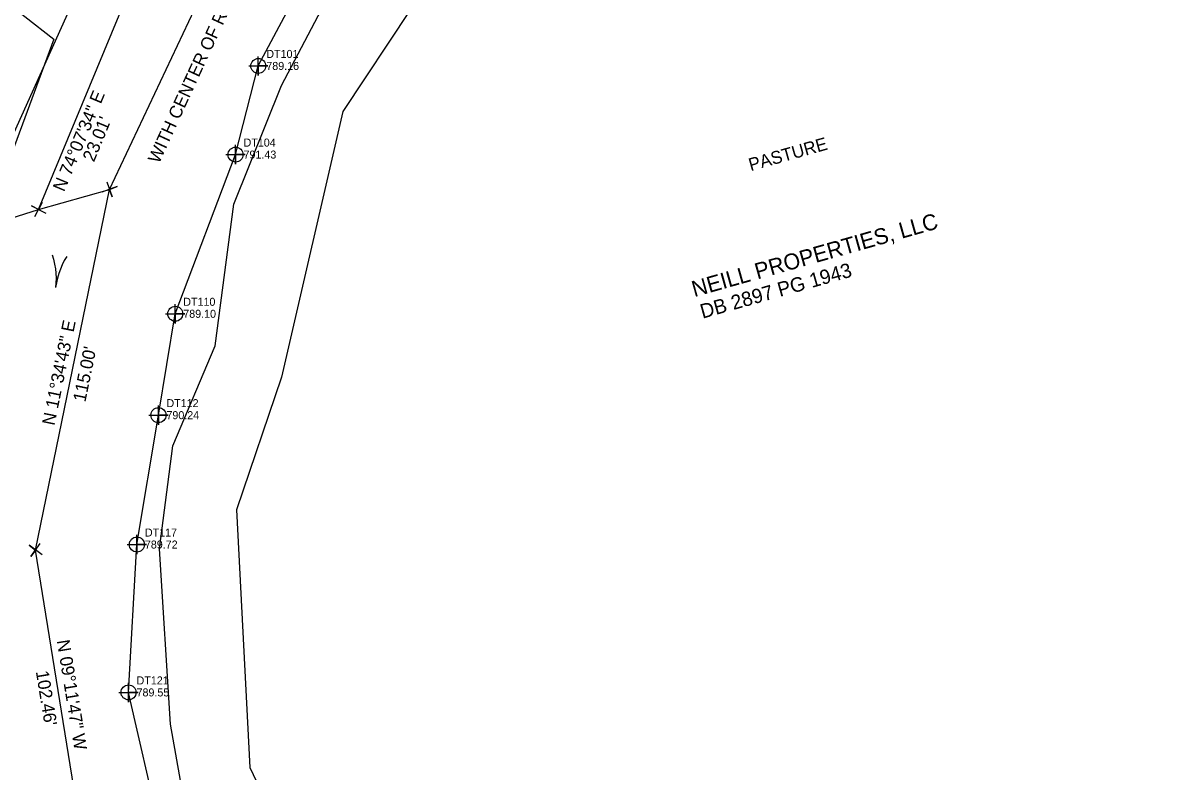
# Model space of a CAD drawing. Extents: x 1316460 to 1321645, y 684173 to 687077.
# Drawn here: x 1319517 to 1319876.5, y 685658.1 to 685892 of the extents above; entities that cross this region are included whole.
import ezdxf

# ---------------------------------------------------------------- set-up
doc = ezdxf.new("R2010")
doc.units = 0
for name, color, linetype in [('Exist Hydro River Flow Arrow CELL', 7, 'Continuous'), ('Exist Hydro Stream Flow Arrow CELL', 7, 'Continuous'), ('Exist Hydro Stream or Body of Water Cogo Elevation', 7, 'Continuous'), ('Exist Hydro Stream or Body of Water Cogo Number', 7, 'Continuous'), ('Exist Hydro Stream or Body of Water Cogo Point CELL', 7, 'Continuous'), ('Exist Hydrographic Water Edge Cogo Elevation', 7, 'Continuous'), ('Exist Property Corner CELL', 7, 'Continuous'), ('Exist Property Deed Book Text', 7, 'Continuous'), ('Exist Property Line', 7, 'Continuous'), ('Exist Property Line Text', 7, 'Continuous'), ('Exist Property Owner Text', 7, 'Continuous'), ('Exist Vegetation Woods Line', 7, 'Continuous'), ('Exist Vegetation Woods Line Text', 7, 'Continuous')]:
    doc.layers.add(name, color=color, linetype=linetype)

# ---------------------------------------------------------------- blocks, each defined once
blk = doc.blocks.new('EXIST HYDRO STREAM FLOW ARROW')
at = {"layer": 'Exist Hydro Stream Flow Arrow CELL'}
blk.add_line((0, 0), (0, 0), dxfattribs=at)
for points in [[(-0.1, 0.04575), (-0.07325, 0.03375), (-0.04475, 0.0245), (-0.0165, 0.01575), (0.01175, 0.0095), (0.041, 0.00475), (0.07075, 0.0015), (0.1, 0)], [(-0.1, -0.04575), (-0.07325, -0.03375), (-0.04475, -0.0245), (-0.0165, -0.01575), (0.01175, -0.0095), (0.041, -0.00475), (0.07075, -0.0015), (0.1, 0)]]:
    blk.add_lwpolyline(points, dxfattribs=at)

msp = doc.modelspace()

# ---------------------------------------------------------------- linework, layer by layer
at = {"layer": 'Exist Hydro Stream or Body of Water Cogo Point CELL'}
for points in [[(1319587.45, 685878.64), (1319593.45, 685878.64), (1319590.45, 685878.64), (1319590.45, 685875.64), (1319590.45, 685881.64)], [(1319580.34, 685850.95), (1319586.34, 685850.95), (1319583.34, 685850.95), (1319583.34, 685847.95), (1319583.34, 685853.95)], [(1319561.51, 685801.22), (1319567.51, 685801.22), (1319564.51, 685801.22), (1319564.51, 685798.22), (1319564.51, 685804.22)], [(1319556.25, 685769.55), (1319562.25, 685769.55), (1319559.25, 685769.55), (1319559.25, 685766.55), (1319559.25, 685772.55)], [(1319549.52, 685729.14), (1319555.52, 685729.14), (1319552.52, 685729.14), (1319552.52, 685726.14), (1319552.52, 685732.14)], [(1319546.92, 685682.94), (1319552.92, 685682.94), (1319549.92, 685682.94), (1319549.92, 685679.94), (1319549.92, 685685.94)]]:
    msp.add_lwpolyline(points, dxfattribs=at)
for centre in [(1319590.45, 685878.64), (1319583.34, 685850.95), (1319564.51, 685801.22), (1319559.25, 685769.55), (1319552.52, 685729.14), (1319549.92, 685682.94)]:
    msp.add_circle(centre, 2.34, dxfattribs=at)
at = {"layer": 'Exist Hydrographic Water Edge Cogo Elevation'}
for points in [[(1319493.49, 685708.97), (1319488.34, 685792.08), (1319503.13, 685833.58), (1319542.31, 685920.28), (1319567.85, 685964.41), (1319601.08, 686016.49), (1319606.48, 686046.34)], [(1319716.21, 685332.36), (1319699.18, 685359.71), (1319690.6, 685372.77), (1319682.76, 685416.6), (1319667.94, 685451.46), (1319627.06, 685524.49), (1319600.93, 685557.74), (1319559.54, 685640.84), (1319549.92, 685682.94), (1319552.52, 685729.14), (1319559.25, 685769.55), (1319564.51, 685801.22), (1319583.34, 685850.95), (1319590.45, 685878.64), (1319637.65, 685967.29), (1319666, 686025.32)]]:
    msp.add_lwpolyline(points, dxfattribs=at)
at = {"layer": 'Exist Property Corner CELL'}
for p, q in [((1319543.95, 685840.09), (1319543.95, 685840.09)), ((1319521.82, 685833.8), (1319521.82, 685833.8)), ((1319520.87, 685727.43), (1319520.87, 685727.43))]:
    msp.add_line(p, q, dxfattribs=at)
for points in [[(1319543.11, 685842.45), (1319544.79, 685837.74), (1319543.95, 685840.09), (1319546.31, 685840.94), (1319541.6, 685839.25)], [(1319520.66, 685831.59), (1319522.98, 685836.01), (1319521.82, 685833.8), (1319519.61, 685834.96), (1319524.03, 685832.64)], [(1319522.9, 685725.97), (1319518.84, 685728.9), (1319520.87, 685727.43), (1319519.41, 685725.41), (1319522.33, 685729.46)]]:
    msp.add_lwpolyline(points, dxfattribs=at)
at = {"layer": 'Exist Property Line'}
for p, q in [((1319521.82, 685833.8), (1319606.18, 686037.65)), ((1319543.95, 685840.09), (1319626.41, 686014.44)), ((1319520.87, 685727.43), (1319543.95, 685840.09)), ((1319521.82, 685833.8), (1319543.95, 685840.09)), ((1319433.34, 685806.22), (1319521.82, 685833.8)), ((1319537.24, 685626.29), (1319520.87, 685727.43))]:
    msp.add_line(p, q, dxfattribs=at)
at = {"layer": 'Exist Vegetation Woods Line'}
for points in [[(1319680.12, 685444.08), (1319660.32, 685489.26), (1319632.72, 685526.95), (1319605.88, 685557.19), (1319586.65, 685593.13), (1319570.35, 685631.98), (1319562.99, 685673.05), (1319559.59, 685727.84), (1319563.8, 685759.98), (1319576.99, 685791.2), (1319582.77, 685835.43), (1319597.74, 685872.49), (1319615.35, 685906.3), (1319629.03, 685935.48), (1319651.09, 685965.06), (1319657.37, 685987.89), (1319700.35, 685977.44), (1319772.19, 685968.73), (1319830.95, 685948.41), (1319900.08, 685923.57), (1319888.58, 685911.13), (1319838.7, 685914.36)], [(1319837.78, 685913.41), (1319687.33, 685939.88), (1319659.12, 685928.27), (1319616.81, 685864.38), (1319597.73, 685781.42), (1319583.62, 685739.93), (1319587.77, 685659.45), (1319630.92, 685569.02), (1319678.21, 685517.58), (1319702.27, 685463.65)], [(1319508.33, 685901.22), (1319526.59, 685886.99), (1319512.87, 685849.7)]]:
    msp.add_lwpolyline(points, dxfattribs=at)

# ---------------------------------------------------------------- block references
at = {"layer": 'Exist Hydro River Flow Arrow CELL', "xscale": 49.99999999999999, "yscale": 50.00000000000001, "rotation": -96.81712222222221}
msp.add_blockref('EXIST HYDRO STREAM FLOW ARROW', (1319527.74, 685814.4), dxfattribs=at)

# ---------------------------------------------------------------- texts
at = {"layer": 'Exist Hydro Stream or Body of Water Cogo Elevation'}
for s, p in [('789.16', (1319592.95, 685877.39)), ('791.43', (1319585.84, 685849.7)), ('789.10', (1319567.01, 685799.97)), ('790.24', (1319561.75, 685768.3)), ('789.72', (1319555.02, 685727.89)), ('789.55', (1319552.42, 685681.69))]:
    msp.add_text(s, height=2.5, dxfattribs=at).set_placement(p)
at = {"layer": 'Exist Hydro Stream or Body of Water Cogo Number'}
for s, p in [('DT101', (1319592.95, 685881.14)), ('DT104', (1319585.84, 685853.45)), ('DT110', (1319567.01, 685803.72)), ('DT112', (1319561.75, 685772.05)), ('DT117', (1319555.02, 685731.64)), ('DT121', (1319552.42, 685685.44))]:
    msp.add_text(s, height=2.5, dxfattribs=at).set_placement(p)
at = {"layer": 'Exist Property Deed Book Text'}
msp.add_text('DB 2897 PG 1943', height=4.5, rotation=15.7349, dxfattribs=at).set_placement((1319729.2, 685799.67))
at = {"layer": 'Exist Property Line Text'}
for s, rotation, p in [('WITH CENTER OF RIVER', 65.2869, (1319559.41, 685847.89)), ('N 74%%D07\'34" E', 67.3621, (1319529.79, 685839.11)), ("23.01'", 67.4773, (1319539.1, 685848.42)), ('N 11%%D34\'43" E', 78.4213, (1319526.76, 685766.14)), ("115.00'", 78.4213, (1319536.43, 685773.47)), ('N 09%%D11\'47" W', 279.1963, (1319527.48, 685699.09)), ("102.46'", 279.1963, (1319520.94, 685689.45))]:
    msp.add_text(s, height=4, rotation=rotation, dxfattribs=at).set_placement(p)
at = {"layer": 'Exist Property Owner Text'}
msp.add_text('NEILL PROPERTIES, LLC', height=5, rotation=15.7349, dxfattribs=at).set_placement((1319726.64, 685806.4))
at = {"layer": 'Exist Vegetation Woods Line Text'}
msp.add_text('PASTURE', height=4, rotation=15.7349, dxfattribs=at).set_placement((1319744.25, 685845.75))

doc.saveas('drawing.dxf')
